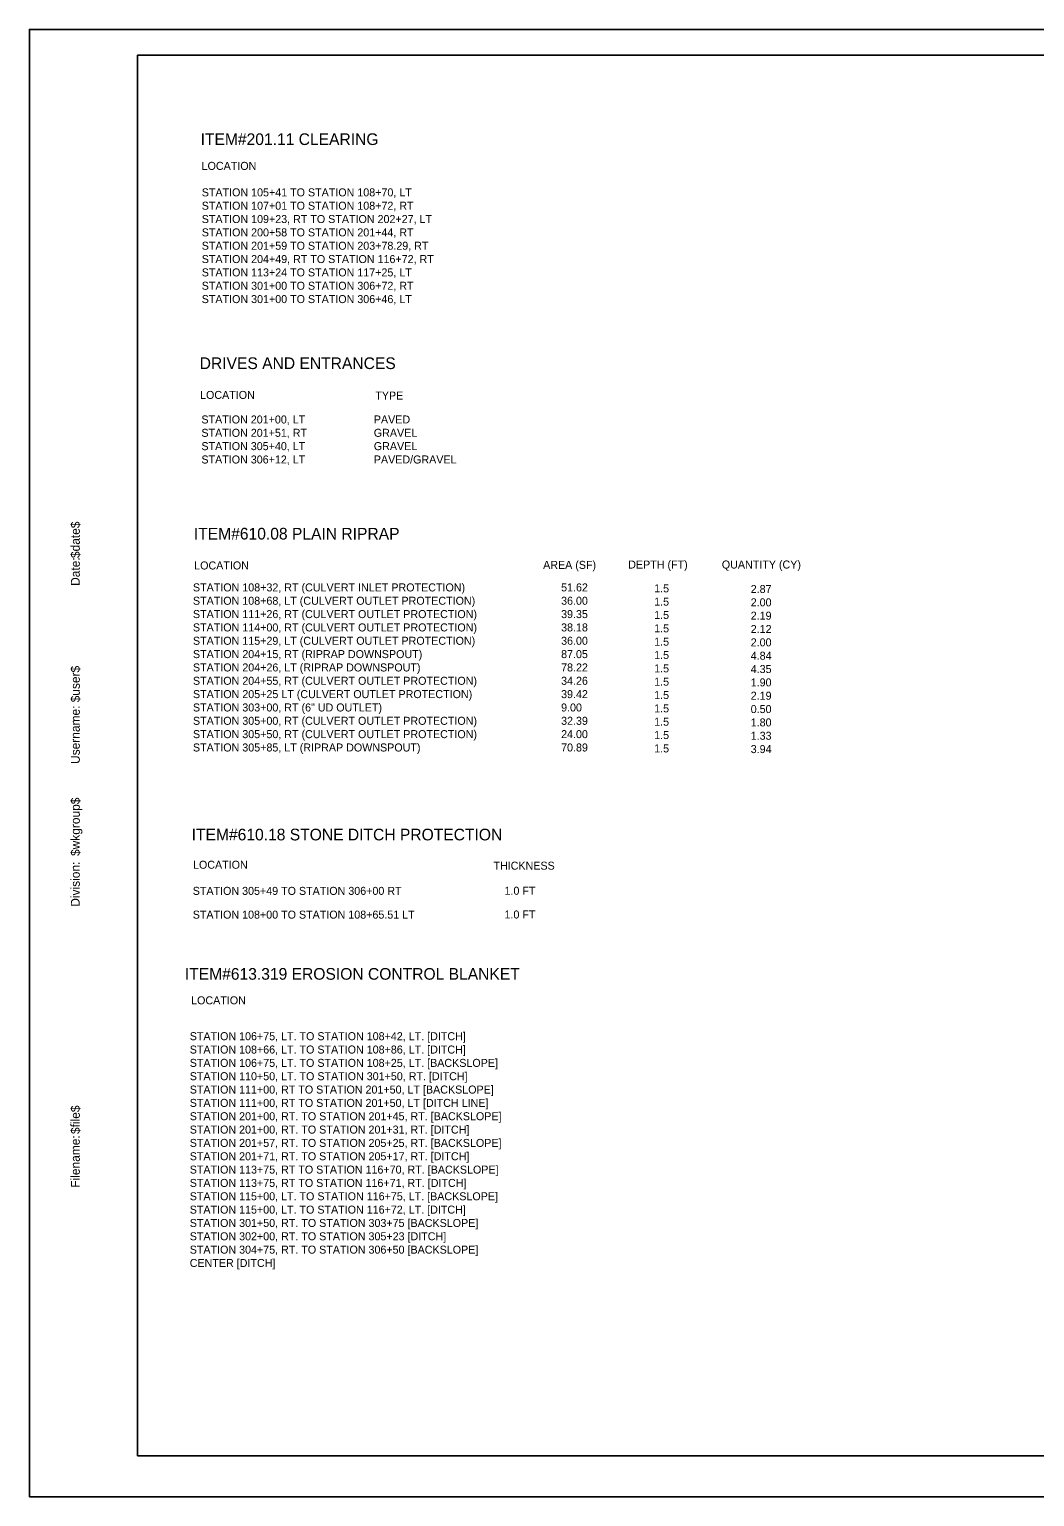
# Model space of a CAD drawing. Extents: x 2075518.1 to 2075585.6, y 1172412.5 to 1172434.5.
# Drawn here: x 2075518.14 to 2075533.2, y 1172412.49 to 1172434.49 of the extents above; entities that cross this region are included whole.
import ezdxf

# ---------------------------------------------------------------- set-up
doc = ezdxf.new("R2010")
doc.units = 0
for name, color, linetype in [('ANNOTATION', 7, 'Continuous'), ('Border', 7, 'Continuous'), ('PLOT BOUNDARY', 7, 'Continuous')]:
    doc.layers.add(name, color=color, linetype=linetype)

msp = doc.modelspace()

# ---------------------------------------------------------------- linework, layer by layer
at = {"layer": 'Border'}
for p, q in [((2075551.755, 1172434.098), (2075519.755, 1172434.098)), ((2075519.755, 1172434.098), (2075519.755, 1172413.098)), ((2075519.755, 1172413.098), (2075551.755, 1172413.098))]:
    msp.add_line(p, q, dxfattribs=at)
at = {"layer": 'PLOT BOUNDARY'}
msp.add_lwpolyline([(2075518.136, 1172412.486), (2075552.136, 1172412.486), (2075552.136, 1172434.486), (2075518.136, 1172434.486)], close=True, dxfattribs=at)

# ---------------------------------------------------------------- texts
at = {"layer": 'ANNOTATION'}
for s, height, p in [('ITEM#201.11 CLEARING', 0.175, (2075520.703, 1172432.752)), ('LOCATION', 0.12, (2075520.718, 1172432.379)), ('STATION 105+41 TO STATION 108+70, LT', 0.12, (2075520.72, 1172431.982)), ('STATION 107+01 TO STATION 108+72, RT', 0.12, (2075520.72, 1172431.782)), ('STATION 109+23, RT TO STATION 202+27, LT', 0.12, (2075520.72, 1172431.582)), ('STATION 200+58 TO STATION 201+44, RT', 0.12, (2075520.72, 1172431.382)), ('STATION 201+59 TO STATION 203+78.29, RT', 0.12, (2075520.72, 1172431.182)), ('STATION 204+49, RT TO STATION 116+72, RT', 0.12, (2075520.72, 1172430.982)), ('STATION 113+24 TO STATION 117+25, LT', 0.12, (2075520.72, 1172430.782)), ('STATION 301+00 TO STATION 306+72, RT', 0.12, (2075520.72, 1172430.582)), ('STATION 301+00 TO STATION 306+46, LT', 0.12, (2075520.72, 1172430.382)), ('DRIVES AND ENTRANCES', 0.175, (2075520.689, 1172429.393)), ('LOCATION', 0.12, (2075520.695, 1172428.945)), ('TYPE', 0.12, (2075523.321, 1172428.936)), ('STATION 201+00, LT', 0.12, (2075520.715, 1172428.577)), ('PAVED', 0.12, (2075523.299, 1172428.577)), ('STATION 201+51, RT', 0.12, (2075520.715, 1172428.377)), ('GRAVEL', 0.12, (2075523.299, 1172428.377)), ('STATION 305+40, LT', 0.12, (2075520.715, 1172428.177)), ('GRAVEL', 0.12, (2075523.299, 1172428.177)), ('STATION 306+12, LT', 0.12, (2075520.715, 1172427.977)), ('PAVED/GRAVEL', 0.12, (2075523.299, 1172427.977)), ('ITEM#610.08 PLAIN RIPRAP', 0.175, (2075520.602, 1172426.837)), ('LOCATION', 0.12, (2075520.607, 1172426.388)), ('AREA (SF)', 0.12, (2075525.837, 1172426.397)), ('DEPTH (FT)', 0.12, (2075527.112, 1172426.402)), ('QUANTITY (CY)', 0.12, (2075528.515, 1172426.402)), ('STATION 108+32, RT (CULVERT INLET PROTECTION)', 0.12, (2075520.588, 1172426.059)), ('STATION 108+68, LT (CULVERT OUTLET PROTECTION)', 0.12, (2075520.588, 1172425.859)), ('51.62', 0.12, (2075526.106, 1172426.059)), ('36.00', 0.12, (2075526.106, 1172425.859)), ('1.5', 0.12, (2075527.501, 1172426.045)), ('2.87', 0.12, (2075528.948, 1172426.035)), ('STATION 111+26, RT (CULVERT OUTLET PROTECTION)', 0.12, (2075520.588, 1172425.659)), ('39.35', 0.12, (2075526.106, 1172425.659)), ('1.5', 0.12, (2075527.501, 1172425.845)), ('1.5', 0.12, (2075527.501, 1172425.645)), ('2.00', 0.12, (2075528.948, 1172425.835)), ('STATION 114+00, RT (CULVERT OUTLET PROTECTION)', 0.12, (2075520.588, 1172425.459)), ('38.18', 0.12, (2075526.106, 1172425.459)), ('1.5', 0.12, (2075527.501, 1172425.445)), ('2.19', 0.12, (2075528.948, 1172425.635)), ('2.12', 0.12, (2075528.948, 1172425.435)), ('STATION 115+29, LT (CULVERT OUTLET PROTECTION)', 0.12, (2075520.588, 1172425.259)), ('36.00', 0.12, (2075526.106, 1172425.259)), ('1.5', 0.12, (2075527.501, 1172425.245)), ('2.00', 0.12, (2075528.948, 1172425.235)), ('STATION 204+15, RT (RIPRAP DOWNSPOUT)', 0.12, (2075520.588, 1172425.059)), ('87.05', 0.12, (2075526.106, 1172425.059)), ('1.5', 0.12, (2075527.501, 1172425.045)), ('4.84', 0.12, (2075528.948, 1172425.035)), ('STATION 204+26, LT (RIPRAP DOWNSPOUT)', 0.12, (2075520.588, 1172424.859)), ('78.22', 0.12, (2075526.106, 1172424.859)), ('1.5', 0.12, (2075527.501, 1172424.845)), ('4.35', 0.12, (2075528.948, 1172424.835)), ('STATION 204+55, RT (CULVERT OUTLET PROTECTION)', 0.12, (2075520.588, 1172424.659)), ('34.26', 0.12, (2075526.106, 1172424.659)), ('1.5', 0.12, (2075527.501, 1172424.645)), ('1.90', 0.12, (2075528.948, 1172424.635)), ('STATION 205+25 LT (CULVERT OUTLET PROTECTION)', 0.12, (2075520.588, 1172424.459)), ('39.42', 0.12, (2075526.106, 1172424.459)), ('1.5', 0.12, (2075527.501, 1172424.445)), ('2.19', 0.12, (2075528.948, 1172424.435)), ('STATION 303+00, RT (6" UD OUTLET)', 0.12, (2075520.588, 1172424.259)), ('9.00', 0.12, (2075526.106, 1172424.259)), ('1.5', 0.12, (2075527.501, 1172424.245)), ('0.50', 0.12, (2075528.948, 1172424.235)), ('STATION 305+00, RT (CULVERT OUTLET PROTECTION)', 0.12, (2075520.588, 1172424.059)), ('32.39', 0.12, (2075526.106, 1172424.059)), ('1.5', 0.12, (2075527.501, 1172424.045)), ('1.80', 0.12, (2075528.948, 1172424.035)), ('STATION 305+50, RT (CULVERT OUTLET PROTECTION)', 0.12, (2075520.588, 1172423.859)), ('STATION 305+85, LT (RIPRAP DOWNSPOUT)', 0.12, (2075520.588, 1172423.659)), ('24.00', 0.12, (2075526.106, 1172423.859)), ('70.89', 0.12, (2075526.106, 1172423.659)), ('1.5', 0.12, (2075527.501, 1172423.845)), ('1.33', 0.12, (2075528.948, 1172423.835)), ('1.5', 0.12, (2075527.501, 1172423.645)), ('3.94', 0.12, (2075528.948, 1172423.635)), ('ITEM#610.18 STONE DITCH PROTECTION', 0.175, (2075520.569, 1172422.326)), ('LOCATION', 0.12, (2075520.589, 1172421.901)), ('THICKNESS', 0.12, (2075525.092, 1172421.887)), ('STATION 305+49 TO STATION 306+00 RT', 0.12, (2075520.585, 1172421.509)), ('1.0 FT', 0.12, (2075525.258, 1172421.511)), ('STATION 108+00 TO STATION 108+65.51 LT', 0.12, (2075520.585, 1172421.153)), ('1.0 FT', 0.12, (2075525.258, 1172421.155)), ('ITEM#613.319 EROSION CONTROL BLANKET', 0.175, (2075520.467, 1172420.237)), ('LOCATION', 0.12, (2075520.561, 1172419.868)), ('STATION 106+75, LT. TO STATION 108+42, LT. [DITCH]', 0.12, (2075520.54, 1172419.33)), ('STATION 108+66, LT. TO STATION 108+86, LT. [DITCH]', 0.12, (2075520.54, 1172419.13)), ('STATION 106+75, LT. TO STATION 108+25, LT. [BACKSLOPE]', 0.12, (2075520.54, 1172418.93)), ('STATION 110+50, LT. TO STATION 301+50, RT. [DITCH]', 0.12, (2075520.54, 1172418.73)), ('STATION 111+00, RT TO STATION 201+50, LT [BACKSLOPE]', 0.12, (2075520.54, 1172418.53)), ('STATION 111+00, RT TO STATION 201+50, LT [DITCH LINE] ', 0.12, (2075520.54, 1172418.33)), ('STATION 201+00, RT. TO STATION 201+45, RT. [BACKSLOPE]', 0.12, (2075520.54, 1172418.13)), ('STATION 201+00, RT. TO STATION 201+31, RT. [DITCH]', 0.12, (2075520.54, 1172417.93)), ('STATION 201+57, RT. TO STATION 205+25, RT. [BACKSLOPE]', 0.12, (2075520.54, 1172417.73)), ('STATION 201+71, RT. TO STATION 205+17, RT. [DITCH]', 0.12, (2075520.54, 1172417.53)), ('STATION 113+75, RT TO STATION 116+70, RT. [BACKSLOPE]', 0.12, (2075520.54, 1172417.33)), ('STATION 113+75, RT TO STATION 116+71, RT. [DITCH]', 0.12, (2075520.54, 1172417.13)), ('STATION 115+00, LT. TO STATION 116+75, LT. [BACKSLOPE]', 0.12, (2075520.54, 1172416.93)), ('STATION 115+00, LT. TO STATION 116+72, LT. [DITCH]', 0.12, (2075520.54, 1172416.73)), ('STATION 301+50, RT. TO STATION 303+75 [BACKSLOPE]', 0.12, (2075520.54, 1172416.53)), ('STATION 302+00, RT. TO STATION 305+23 [DITCH]', 0.12, (2075520.54, 1172416.33)), ('STATION 304+75, RT. TO STATION 306+50 [BACKSLOPE]', 0.12, (2075520.54, 1172416.13)), ('CENTER [DITCH]', 0.12, (2075520.54, 1172415.93))]:
    msp.add_text(s, height=height, dxfattribs=at).set_placement(p)
at = {"layer": 'Border'}
for s, p in [('$date$', (2075518.892, 1172426.559)), ('Date:', (2075518.892, 1172426.142)), ('$user$', (2075518.892, 1172424.396)), ('Username:', (2075518.892, 1172423.472)), ('$wkgroup$', (2075518.892, 1172422.092)), ('Division:', (2075518.892, 1172421.331)), ('$file$', (2075518.892, 1172417.923)), ('Filename:', (2075518.892, 1172417.118))]:
    msp.add_text(s, height=0.1339, rotation=90, dxfattribs=at).set_placement(p)

doc.saveas('drawing.dxf')
